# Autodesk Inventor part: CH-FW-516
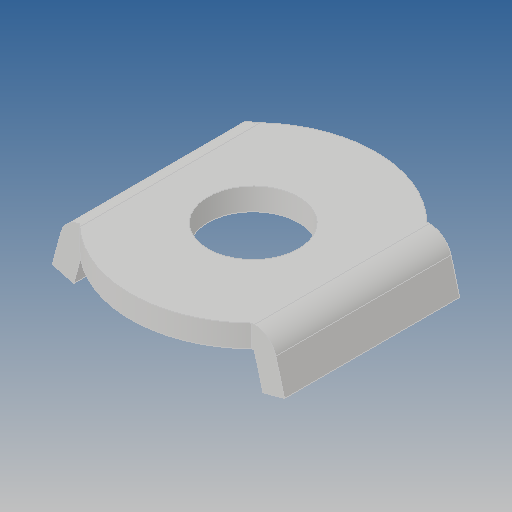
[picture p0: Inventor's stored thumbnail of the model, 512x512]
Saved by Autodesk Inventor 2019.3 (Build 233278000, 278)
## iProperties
Created: 2017-11
Part Number: CH-FW-516
Material: Ogólny
Document SubType Name: Modeling
Designer: Admin
Density: 1 g/cm^3
Appearance: Domyślna
Author: Admin
Revision Number: ÈÎºÎ
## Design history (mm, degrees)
feature "ÇÐ³ý-À­Éì3"
node "Bryła1"
